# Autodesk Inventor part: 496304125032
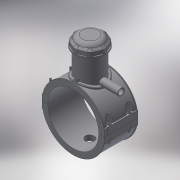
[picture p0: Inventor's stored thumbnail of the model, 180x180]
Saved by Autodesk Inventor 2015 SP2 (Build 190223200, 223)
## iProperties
Created: 2017-07
Part Number: 496304125032
Material: Generic
Description: PLASSON TAPPING SADDLE 125x32
Document SubType Name: Modeling
Designer: KIM
Mass: 823.44 g
Surface Area: 1846.73 cm^2
Volume: 823.44 cm^3
Density: 1 g/cm^3
Appearance: Default
Author: KIM
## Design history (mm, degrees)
derived "496304.ipt"
feature "Solid1::496304.ipt"
feature "Solid2::496304.ipt"
feature "Solid4::496304.ipt"
feature "Solid5::496304.ipt"
tag "TaggingFeature1"
body "Solid1"
body "Solid2"
other parameters: "d0" = 125, "d2" = 162, "d3" = 31.25, "d4" = 118, "d5" = 0, "d6" = 0.1, "d8" = 0, "d19" = 6, "d20" = 6, "d21" = 70.8, "d23" = 0, "d24" = 35.4, "d26" = 0, "d29" = 3, "d30" = 41.66667, "d31" = 6, "d32" = 0, "d33" = 0, "d34" = 0.6, "d40" = 78, "d41" = 62.5, "d43" = 0, "d45" = 0, "d47" = 145.8, "d70" = 15, "d72" = 0, "d73" = 6, "d75" = 5, "d76" = 0, "d77" = 6.25, "d78" = 92.5, "d79" = 15, "d80" = 47.2, "d82" = 5 deg, "d84" = 4, "d85" = 14, "d86" = 0, "d87" = 3, "d88" = 0, "d89" = 1, "d90" = 1, "d91" = 94.4, "d92" = 0, "d93" = 0.5, "d94" = 65.78947, "d96" = 153, "d97" = 2.36, "d98" = 0, "d102" = 1.25, "d120" = 140 deg, "d121" = 24.228, "d122" = 20 deg, "d126" = 0, "d143" = 128.75, "d145" = 19.23077, "d149" = 1.875, "d150" = 21.15385, "d153" = 118, "d154" = 0, "d156" = 75, "d157" = 160 deg, "d159" = 5, "d161" = 1.875, "d162" = 70.8, "d163" = 0, "d164" = 62.5, "d167" = 12.5, "d168" = 73.17073, "d170" = 3.375, "d172" = 0, "d173" = 1, "d175" = 62.5, "d176" = 20 deg, "d177" = 8.75, "d178" = 25, "d180" = 0, "d184" = 7, "d185" = 38.35, "d186" = 38.35, "d187" = 75, "d188" = 7.5, "d189" = 8.75, "d190" = 0, "d191" = 112.5, "d193" = 6.3, "d194" = 4.13, "d195" = 90 deg, "d197" = 0, "d199" = 0, "d200" = 12.5, "d202" = 0, "d203" = 114, "d204" = 59.375, "d205" = 43.75, "d206" = 53.125, "d207" = 85.5, "d208" = 88.92, "d209" = 106.02, "d210" = 53.75, "d211" = 62.5, "d213" = 0, "d216" = 0, "d217" = 12.5, "d218" = 12.5, "d219" = 2.5, "d222" = 125, "d224" = 0, "d230" = 5, "d233" = 6, "d236" = 81, "d237" = 35.4, "d238" = 6.02433, "d240" = 35.4, "d241" = 35.4, "d242" = 35.4, "d243" = 6, "d244" = 35.4, "d245" = 35.4, "d246" = 35.4, "d247" = 6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
